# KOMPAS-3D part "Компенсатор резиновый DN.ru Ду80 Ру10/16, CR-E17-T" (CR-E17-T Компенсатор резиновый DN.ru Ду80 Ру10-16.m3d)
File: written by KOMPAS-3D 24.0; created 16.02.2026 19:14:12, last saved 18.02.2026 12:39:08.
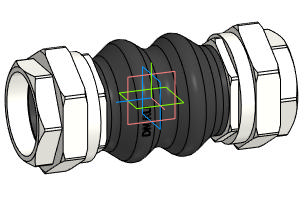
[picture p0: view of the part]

Document properties: Автор: DN.RU; Полное имя файла: CR-E17-T Компенсатор резиновый DN.ru Ду80 Ру10-16.cdw

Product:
- Body: Твердое тело1  | qty 1
    Масса: 9.100291
- Part/product: Компенсатор резиновый DN.ru Ду80 Ру10/16  | designation CR-E17-T
    Масса: 3.2
    Раздел спецификации: Прочие изделия
    Форматы листов документа: A3
    Комментарий: D140-02406
    Примечание: D140-02406
    additional columns: Типовые

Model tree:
1. Твердое тело1  (labels: Твердое тело1)

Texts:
  CR-E17-T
